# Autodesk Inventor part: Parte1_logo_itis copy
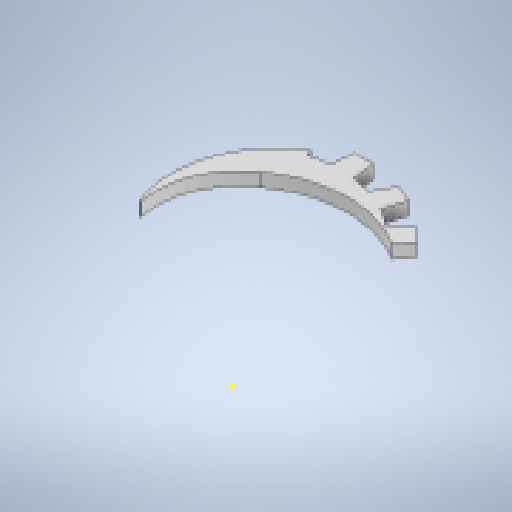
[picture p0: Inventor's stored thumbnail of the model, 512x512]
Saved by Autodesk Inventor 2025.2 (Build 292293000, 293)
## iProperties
Created: 2025-03
Part Number: Parte1_logo_itis copy
Material: Generico
Document SubType Name: Modeling
Designer: 18907419
Density: 1 g/cm^3
Appearance: Default
Author: 18907419
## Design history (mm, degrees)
sketch "Schizzo1"
  geometry: L1 (0, 0)-(198.619, 0); L2 (198.619, 0)-(198.619, -200); L3 (198.619, -200)-(0, -200); L4 (0, -200)-(0, 0); 1 other entity
  constraints: 2 other
  dimensions: "d1" = 200 distance of L3.end L1.start
  node "Immagine1"
sketch "Schizzo2"
  geometry: L1 (105.821, -199.217)-(91.821, -199.217); L2 (91.821, -199.217)-(89.861, -182.291); L3 (98.821, -199.217)-(98.821, -182.907); L4 (105.821, -199.217)-(107.782, -182.291); L5 (143.188, -189.466)-(130.253, -194.824); L6 (130.253, -194.824)-(121.965, -179.936); L7 (136.721, -192.145)-(130.479, -177.077); L8 (143.188, -189.466)-(138.521, -173.078); L9 (173.978, -166.158)-(164.079, -176.058); L10 (164.079, -176.058)-(150.724, -165.475); L11 (169.028, -171.108)-(157.495, -159.575); L12 (173.978, -166.158)-(163.395, -152.804); L13 (193.505, -132.842)-(188.148, -145.776); L14 (188.148, -145.776)-(171.76, -141.109); L15 (190.826, -139.309)-(175.758, -133.067); L16 (193.505, -132.842)-(178.617, -124.553); L17 (198.796, -94.588)-(198.796, -108.588); L18 (198.796, -108.588)-(181.87, -110.548); L19 (198.796, -101.588)-(182.486, -101.588); L20 (198.796, -94.588)-(181.87, -92.628); L21 (189.045, -57.222)-(194.403, -70.156); L22 (194.403, -70.156)-(179.515, -78.445); L23 (191.724, -63.689)-(176.655, -69.931); L24 (189.045, -57.222)-(172.657, -61.888); L25 (165.737, -26.431)-(175.637, -36.331); L26 (175.637, -36.331)-(165.054, -49.686); L27 (170.687, -31.381)-(159.154, -42.914); L28 (165.737, -26.431)-(152.382, -37.014); L29 (132.42, -6.904)-(145.355, -12.262); L30 (145.355, -12.262)-(140.688, -28.65); L31 (138.888, -9.583)-(132.646, -24.652); L32 (132.42, -6.904)-(124.132, -21.792); L33 (94.167, -1.614)-(108.167, -1.614); L34 (108.167, -1.614)-(110.127, -18.54); L35 (101.167, -1.614)-(101.167, -17.924); L36 (94.167, -1.614)-(92.207, -18.54); L37 (56.801, -11.364)-(69.735, -6.007); L38 (69.735, -6.007)-(78.023, -20.895); L39 (63.268, -8.686)-(69.51, -23.754); L40 (56.801, -11.364)-(61.467, -27.753); L41 (26.01, -34.672)-(35.91, -24.773); L42 (35.91, -24.773)-(49.265, -35.356); L43 (30.96, -29.723)-(42.493, -41.256); L44 (26.01, -34.672)-(36.593, -48.027); L45 (6.483, -67.989)-(11.841, -55.055); L46 (11.841, -55.055)-(28.229, -59.721); L47 (9.162, -61.522)-(24.231, -67.764); L48 (6.483, -67.989)-(21.371, -76.278); L49 (1.192, -106.243)-(1.192, -92.243); L50 (1.192, -92.243)-(18.119, -90.283); L51 (1.192, -99.243)-(17.503, -99.243); L52 (1.192, -106.243)-(18.119, -108.203); L53 (10.943, -143.609)-(5.586, -130.675); L54 (5.586, -130.675)-(20.474, -122.386); L55 (8.264, -137.142)-(23.333, -130.9); L56 (10.943, -143.609)-(27.331, -138.942); L57 (34.251, -174.399)-(24.352, -164.5); L58 (24.352, -164.5)-(34.935, -151.145); L59 (29.301, -169.45)-(40.835, -157.917); L60 (34.251, -174.399)-(47.606, -163.816); L61 (67.568, -193.926)-(54.634, -188.569); L62 (54.634, -188.569)-(59.3, -172.181); L63 (61.101, -191.248)-(67.343, -176.179); L64 (67.568, -193.926)-(75.856, -179.038); A1 r 82.5 centre (99.994, -100.415) between (89.861, -182.291) and (98.821, -182.907); A2 r 80 centre (81.89, -116.945) between (124.568, -184.611) and (153.002, -80.297); A3 r 85 centre (79.253, -82.612) between (32.823, -153.81) and (129.534, -151.145); A4 r 61.843 centre (94.454, -100.214) between (129.534, -151.145) and (153.002, -80.297); A5 r 55 centre (101.821, -141.774) between (127.729, -190.29) and (140.688, -180.688); 9 further points
  constraints: 128 end point, 11 point on circle, 5 centre point, 4 point on line, 1 horizontal, 1 midpoint, 1 symmetric about line, 1 vertical, 161 other
  dimensions: "d2" = 165 diameter of A1; "d3" = 14 distance of L1.start L1.end; "d6" = 360 deg dimension on A1.centre L1.start (derived); "d8" = 80 radius of A2; "d14" = 55 radius of A5
extrude "Estrusione1" new body sketch "Schizzo2" distance "d10" = 10; taper "d11" = 0 deg
fillet "Raccordo1" dims "d13" = 0.6
sketch "Schizzo3"
  geometry: 1 further point
sketch "Schizzo4"
  geometry: L1 (-143.188, 189.466)-(-140.688, 180.688) reference; L2 (-127.729, 190.29)-(-130.253, 194.824) reference; L3 (-130.253, 194.824)-(-143.188, 189.466) reference; A1 r 55 centre (-101.821, 141.774) between (-127.729, 190.29) and (-140.688, 180.688) reference; 1 further point
extrude "Estrusione2" cut sketch "Schizzo4" distance "d15" = 10; taper "d16" = 0 deg
node "Solido1"
node "Schizzo - Serie circolare1" dims "d6" = 360 deg (derived)
node "Linea chiusa proiettata1"
